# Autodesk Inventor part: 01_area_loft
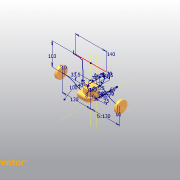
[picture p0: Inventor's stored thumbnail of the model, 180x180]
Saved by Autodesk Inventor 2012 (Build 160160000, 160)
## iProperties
Created: 2002-07
Part Number: 01_area_loft
Document SubType Name: Modeling
Designer: Lieven Grauls
Project: Valve Techcamp 2008
Density: 1 g/cm^3
Mass: 187.687 g
Surface Area: 269.927 cm^2
Volume: 187.687 cm^3
Material: Default
Company: Autodesk
Control State: 0
Master: False
Checked Out: False
Shininess: 64.0
Length Units: 11269
Angle Units: 11279
Time Units: 11290
Mass Units: 11283
Length Display Precision: 3
Angle Display Precision: 2
Density: 0.0
Volumn: 0.0
Area: 0.0
PropertySet Name: Model Information
Author: Lieven Grauls
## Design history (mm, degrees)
sketch "Sketch2"
  geometry: L1 (-130, 0)-(-120, 0); L2 (130, 0)-(120, 0); L3 (38.866, 33.5)-(23.866, 33.5); L4 (-70, 103)-(70, 103); L5 (0, -142.6)-(0, 155.6) reference; L6 (-40.156, -25)-(0, -25); A1 r 100 centre (-120, -100) between (-62.969, -17.857) and (-120, 0); A2 r 40 centre (-40.156, 15) between (-62.969, -17.857) and (-40.156, -25); A3 r 70 centre (120, 70) between (70.614, 20.391) and (120, 0); A4 r 45 centre (38.866, -11.5) between (70.614, 20.391) and (38.866, 33.5); 4 further points
  constraints: 10 end point, 8 point on circle, 6 tangent, 4 centre point, 3 horizontal, 2 horizontal alignment, 2 perpendicular, 2 point on line, 1 midpoint, 1 other
  dimensions: "d8" = 130 distance of L1.start point (0, 0); "d9" = 100 radius of A1; "d10" = 40 radius of A2; "d15" = 130 distance of L2.start point (0, 0) (= d8); "d16" = 70 radius of A3; "d61" = 33.5 distance of the line from the sketch origin of L3; "d63" = 45 radius of A4; "d102" = 10 distance of L1.start L1.end; "d103" = 10 distance of L2.start L2.end; "d182" = 15 distance of L3.start L3.end; "d220" = 103 distance of the line from the sketch origin of L4; "d221" = 140 distance of L4.start L4.end; "d249" = 25 distance of the line from the sketch origin of L6
sketch "Sketch15"
  geometry: L1 (-80, 100)-(-46.5, 100); L2 (-37.013, 96.7)-(-37.013, 60); L3 (-37.013, 60)-(-35.513, 60); L4 (-80, 113)-(-80, 100); L5 (-46.5, 100)-(-46.5, 96.7); L6 (-46.5, 96.7)-(-37.013, 96.7); L7 (0, -142.6)-(0, 155.6) reference; L8 (-209.58, 0)-(186.597, 0) reference; L9 (-35.513, 60)-(-35.513, 0); L10 (-35.513, 0)-(0, 0)
  constraints: 16 end point, 4 perpendicular, 2 vertical, 1 collinear, 1 horizontal, 1 parallel, 1 point on line
  dimensions: "d233" = 3.3 distance between parallel lines of L6 L1; "d237" = 100 distance between parallel lines of L1 L8; "d238" = 60 distance between parallel lines of L8 L3; "d239" = 93 diameter of L5 L7; "d240" = 74.025 diameter of L2 L7; "d241" = 71.025 diameter of L9 L7; "d242" = 160 diameter of L4 L7
workplane "Work Plane6"
workplane "Work Plane2"
workplane "Work Plane1"
workplane "Work Plane12"
workplane "Work Plane5"
sketch "Sketch6"
  geometry: C1 r 25.5 at (0, 0); 1 further point
  constraints: 1 centre point, 1 coincident
  dimensions: "d25" = 51 diameter of C1
sketch "Sketch5"
  geometry: C1 r 25.5 at (0, 0); 1 further point
  constraints: 1 centre point, 1 coincident
  dimensions: "d24" = 51 diameter of C1
sketch "Sketch11"
  geometry: C1 r 25.5 at (0, 0); 1 further point
  constraints: 1 centre point, 1 coincident
  dimensions: "d104" = 51 diameter of C1 (= d24)
sketch "Sketch7"
  geometry: L1 (0, -142.6)-(0, 155.6) reference; L2 (-32.5, 103)-(-32.5, 74); L3 (-32.5, 74)-(-45.093, 69.417); L4 (-32.5, 8)-(0, 8); L5 (0, 103)-(-32.5, 103); L6 (-46.873, 22.579)-(-39.053, 11.411); L7 (-209.58, 0)-(186.597, 0) reference; A1 r 18 centre (-38.936, 52.502) between (-45.093, 69.417) and (-56.906, 51.462); A2 r 56 centre (-1, 54.699) between (-56.906, 51.462) and (-46.873, 22.579); A3 r 8 centre (-32.5, 16) between (-39.053, 11.411) and (-32.5, 8); 1 further point
  constraints: 10 end point, 6 point on circle, 5 point on line, 5 tangent, 3 centre point, 2 perpendicular, 1 horizontal, 1 parallel
  dimensions: "d28" = 65 diameter of L2 L1; "d30" = 110 deg angle of L2 L3; "d31" = 18 radius of A1; "d32" = 56 radius of A2; "d41" = 55 deg angle of L4 L6; "d65" = 8 radius of A3; "d135" = 103 distance between parallel lines of L7 L5; "d136" = 29 distance of L2.start L2.end; "d137" = 8 distance between parallel lines of L7 L4; "d138" = 1 distance from line of A2.centre L1; "d139" = 65 diameter of A3.centre L1
sketch "Sketch1"
  geometry: L1 (70, 103)-(70, 55); L2 (57.702, 15.997)-(40.477, -8.604); L3 (0, -142.6)-(0, 155.6) reference; L4 (28.19, -15)-(15, -15); L5 (-209.58, 0)-(186.597, 0) reference; L6 (-209.58, 103)-(186.597, 103) reference; A1 r 68 centre (2, 55) between (57.702, 15.997) and (70, 55); A2 r 15 centre (28.19, 0) between (28.19, -15) and (40.477, -8.604); 1 further point
  constraints: 6 end point, 4 point on circle, 4 tangent, 2 centre point, 1 perpendicular, 1 point on line
  dimensions: "d1" = 140 diameter of L1 L3; "d4" = 68 radius of A1; "d5" = 35 deg angle of L1 L2; "d217" = 15 distance between parallel lines of L4 L5; "d218" = 15 radius of A2; "d222" = 48 distance of L1.start L1.end; "d229" = 15 distance from line of L3 L4.end
workplane "Work Plane10"
sketch "Sketch17"
  geometry: L1 (-9, 25.5)-(-15.5, 32); L2 (-15.5, 32)-(-16.5, 32); L3 (-9, 25.5)-(-9, 0); L4 (-142.6, 0)-(155.6, 0) reference; L5 (0, -57.824)-(0, 57.824) reference; A1 r 32 centre (-16.5, 0) between (-16.5, 32) and (-48.5, 0)
  constraints: 6 end point, 3 point on line, 2 perpendicular, 2 point on circle, 1 centre point, 1 tangent
  dimensions: "d250" = 32 radius of A1; "d252" = 45 deg angle of L3 L1; "d253" = 1 distance of L1.end L2.end; "d286" = 9 distance between parallel lines of L5 L3; "d287" = 25.5 distance from line of L4 L1.start
revolve "Revolution6" sketch "Sketch17" stored, may be unused: angle "d255" = 180 deg
sketch "Sketch19"
  geometry: L1 (32, 1)-(32, 0) reference; L2 (25.5, 7.5)-(32, 1) reference; L3 (-25.5, 7.5)-(25.5, 7.5) reference; L4 (-32, 1)-(-25.5, 7.5) reference; L5 (-32, 0)-(-32, 1) reference; A1 r 32 centre (0, 0) between (-32, 0) and (32, 0) reference; 1 further point
extrude "Extrusion4" join sketch "Sketch19" distance "d257" = 26; taper "d258" = 0 deg
fillet "Fillet11" dims "d259" = 8
extrude "Extrusion5" join sketch "Sketch11" stored distance "d260" = 30; taper "d261" = 0 deg
extrude "Extrusion2" join sketch "Sketch5" distance "d159" = 10; taper "d160" = 0 deg
extrude "Extrusion3" join sketch "Sketch6" distance "d183" = 10; taper "d184" = 0 deg
feature "srf_outerskin" [RevolutionSrf] dims angle "d219" = 90 deg
sketch "section_loft2"
  geometry: L1 (-122.1, 0)-(176.1, 0) reference; L2 (-15, -35)-(-15, 35); L3 (15, 25)-(15, -25); A1 r 56 centre (-19.319, 15.141) between (-9.086, -39.916) and (11.386, -31.69); A2 r 56 centre (-19.319, -15.141) between (11.386, 31.69) and (-9.086, 39.916); A3 r 5 centre (-10, 35) between (-9.086, 39.916) and (-15, 35); A4 r 5 centre (-10, -35) between (-15, -35) and (-9.086, -39.916); A5 r 8 centre (7, 25) between (15, 25) and (11.386, 31.69); A6 r 8 centre (7, -25) between (11.386, -31.69) and (15, -25); 2 further points
  constraints: 12 point on circle, 8 tangent, 6 centre point, 4 end point, 3 equal radius, 1 parallel, 1 perpendicular
  dimensions: "d144" = 15 distance from line of point (0, 0) L2 (= 0.5 x d145); "d145" = 30 distance between parallel lines of L2 L3; "d146" = 56 radius of A1; "d147" = 5 radius of A3; "d148" = 70 distance of A3.centre A4.centre; "d149" = 35 distance from line of L1 A4.centre (= 0.5 x d148); "d150" = 50 distance of A5.centre A6.centre; "d151" = 25 distance from line of L1 A6.centre (= 0.5 x d150); "d152" = 8 radius of A5
sketch "section_loft3"
  geometry: L1 (-313.192, 0)-(177.649, 0) reference; L2 (17.5, -17.5)-(17.5, 17.5); L3 (2.5, 32.5)-(-2.5, 32.5); L4 (-17.5, 17.5)-(-17.5, -17.5); L5 (-2.5, -32.5)-(2.5, -32.5); A1 r 15 centre (2.5, 17.5) between (17.5, 17.5) and (2.5, 32.5); A2 r 15 centre (2.5, -17.5) between (2.5, -32.5) and (17.5, -17.5); A3 r 15 centre (-2.5, -17.5) between (-17.5, -17.5) and (-2.5, -32.5); A4 r 15 centre (-2.5, 17.5) between (-2.5, 32.5) and (-17.5, 17.5); 5 further points
  constraints: 8 end point, 8 point on circle, 8 tangent, 6 point on line, 4 centre point, 3 equal radius, 2 parallel, 2 perpendicular
  dimensions: "d368" = 65 distance of point (17.5, -32.5) point (17.5, 32.5); "d369" = 35 distance of point (17.5, 32.5) point (-17.5, 32.5); "d370" = 32.5 distance between parallel lines of L1 L3 (derived); "d371" = 17.5 distance from line of point (0, 0) L4 (derived); "d372" = 15 radius of A1
revolve "Revolution5" stored, may be unused: angle "d212" = 90 deg
sketch "Sketch8"
  geometry: L1 (-130, 85.5)-(-110, 85.5); L2 (-130, 85.5)-(-132.392, 17.012); L3 (-110, 85.5)-(-108.763, 14.622); L4 (-209.58, 0)-(186.597, 0) reference; L5 (-130, 155.6)-(-130, -142.6) reference
  constraints: 6 end point, 1 parallel, 1 point on line
  dimensions: "d47" = 20 distance of L1.start L1.end; "d223" = 92 deg angle of L4 L2; "d226" = 171 diameter of L1 L4; "d227" = 91 deg angle of L1 L3
feature "RevolutionSrf2" sketch "Sketch8" dims angle "d228" = 90 deg
mirror "Mirror1"
sketch "Sketch20"
  geometry: L1 (-128, 77.5)-(-114, 77.5); L2 (-114, 77.5)-(-114, 45); L3 (-114, 45)-(-107, 45); L4 (-107, 45)-(-107, 100.638); L5 (-128, 77.5)-(-128, 48); L6 (-128, 48)-(-130, 48); L7 (-130, 48)-(-130, 0); L8 (0, -142.6)-(0, 155.6) reference; L9 (-209.58, 0)-(186.597, 0) reference; L10 (-130, 0)-(-152.983, 0)
  constraints: 16 end point, 4 parallel, 2 collinear, 2 perpendicular
  dimensions: "d290" = 16 distance between parallel lines of L2 L7; "d292" = 2 distance between parallel lines of L7 L5; "d306" = 155 diameter of L1 L9; "d307" = 96 diameter of L6 L9; "d308" = 90 diameter of L3 L9; "d309" = 130 distance between parallel lines of L8 L7; "d310" = 7 distance of L2.end L3.end
node "Volumenkörper1"
node "Volumenkörpern"
node "Oberflächenkörpern"
node "Flächen1"
node "Flächen2"
node "Flächen3"
feature "RevolutionSrf3"
other parameters: "d285" = -5, "d409" = 0.5, "d410" = 2, "d411" = 0
